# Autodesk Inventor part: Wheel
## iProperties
Created: 2008-06
Part Number: Wheel
Document SubType Name: Modeling
Designer: CADCIM
Density: 1 g/cm^3
Author: CADCIM
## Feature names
1. Revolution1
2. Extrusion1
3. Fillet1
4. Fillet2
5. Circular Pattern1
6. Chamfer1
7. Fillet3
8. Fillet4
9. Fillet5
